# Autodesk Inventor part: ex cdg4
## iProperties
Author: jost thierry
Created: 2004-05
Part Number: ex cdg4
Material: Titane
Document SubType Name: Modélisation
Designer: jost thierry
Control State: 0
Master: False
Checked Out: False
PropertySet Name: Design Tracking Control
Shininess: 20.0
Angle Display Precision: 2
Document Length Units: 11269
Document Angle Units: 11283
Document Time Units: 11279
Document Mass Units: 11290
Document Length Units Precision: 3
Document Angle Units Precision: 2
Compacted: False
PropertySet Name: _Private Model Information
Density: 4.51
Volumn: 58.43362938564081
Area: 165.4336293856408
PropertySet Name: Model Information
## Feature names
1. Extrusion1
